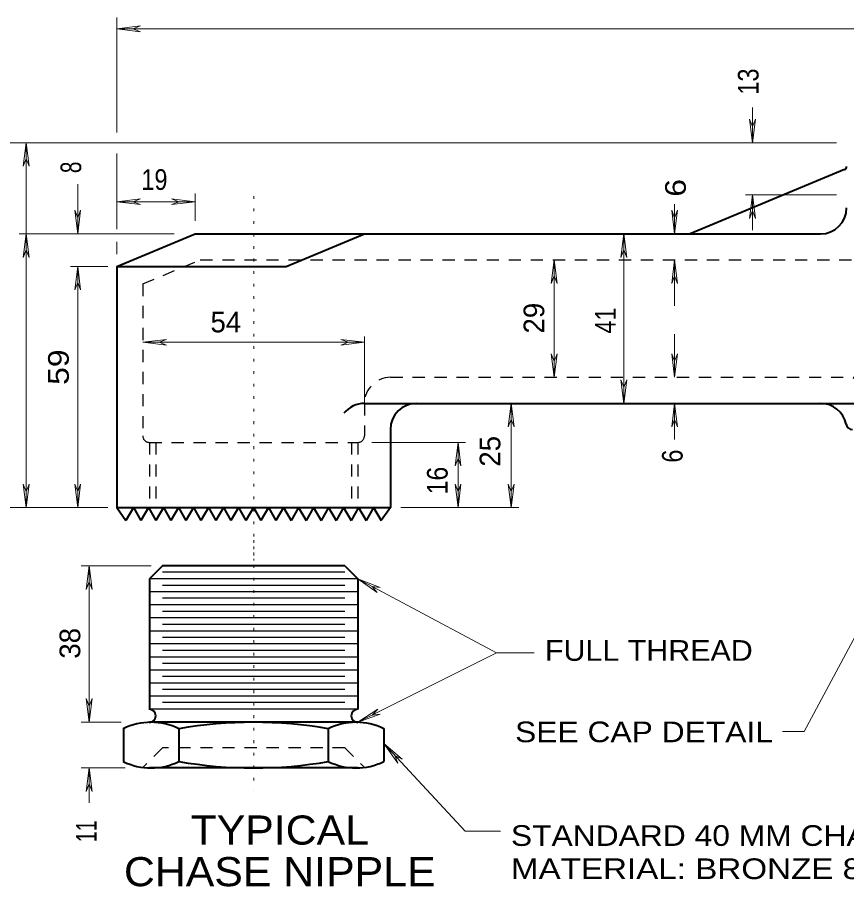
# Model space of a CAD drawing. Extents: x 312583 to 312854, y 144419 to 144597.
# Drawn here: x 312620.73 to 312651.22, y 144522.17 to 144554.13 of the extents above; entities that cross this region are included whole.
import ezdxf
from ezdxf.enums import TextEntityAlignment as Align

# ---------------------------------------------------------------- set-up
doc = ezdxf.new("R2010")
doc.units = 0
doc.header["$LTSCALE"] = 0.3
doc.linetypes.add('DOTTED', pattern=[1.5, 0.3, -1.2])
doc.linetypes.add('SHORT_DASHED', pattern=[2.7, 1.5, -1.2])
doc.layers.add('1', color=7, linetype='Continuous', lineweight=40)
doc.layers.add('2', color=7, linetype='Continuous', lineweight=13)

msp = doc.modelspace()

# ---------------------------------------------------------------- linework, layer by layer
at = {"layer": '1'}
for p, q in [((312651.1474, 144548.5342), (312645.4741, 144546.1729)), ((312624.3907, 144544.9769), (312627.2657, 144546.1729)), ((312627.2657, 144546.1729), (312650.2657, 144546.1729)), ((312630.6161, 144544.9769), (312633.4911, 144546.1729)), ((312624.3907, 144544.9769), (312630.6161, 144544.9769)), ((312633.4911, 144539.9399), (312651.6457, 144539.9399)), ((312634.4494, 144538.9815), (312634.4494, 144536.1065)), ((312624.3907, 144536.1065), (312624.7204, 144535.6312)), ((312624.9964, 144536.1065), (312624.7204, 144535.6312)), ((312624.9964, 144536.1065), (312625.2724, 144535.6312)), ((312625.5484, 144536.1065), (312625.2724, 144535.6312)), ((312625.5484, 144536.1065), (312625.8244, 144535.6312)), ((312626.1004, 144536.1065), (312625.8244, 144535.6312)), ((312626.1004, 144536.1065), (312626.3764, 144535.6312)), ((312626.6524, 144536.1065), (312626.3764, 144535.6312)), ((312626.6524, 144536.1065), (312626.9284, 144535.6312)), ((312627.2044, 144536.1065), (312626.9284, 144535.6312)), ((312627.2044, 144536.1065), (312627.4804, 144535.6312)), ((312627.7564, 144536.1065), (312627.4804, 144535.6312)), ((312627.7564, 144536.1065), (312628.0324, 144535.6312)), ((312628.3084, 144536.1065), (312628.0324, 144535.6312)), ((312628.3084, 144536.1065), (312628.5844, 144535.6312)), ((312628.8604, 144536.1065), (312628.5844, 144535.6312)), ((312628.8604, 144536.1065), (312629.1364, 144535.6312)), ((312629.4124, 144536.1065), (312629.1364, 144535.6312)), ((312629.4124, 144536.1065), (312629.6884, 144535.6312)), ((312629.9644, 144536.1065), (312629.6884, 144535.6312)), ((312629.9644, 144536.1065), (312630.2404, 144535.6312)), ((312630.5164, 144536.1065), (312630.2404, 144535.6312)), ((312630.5164, 144536.1065), (312630.7924, 144535.6312)), ((312631.0684, 144536.1065), (312630.7924, 144535.6312)), ((312631.0684, 144536.1065), (312631.3444, 144535.6312)), ((312631.6204, 144536.1065), (312631.3444, 144535.6312)), ((312631.6204, 144536.1065), (312631.8964, 144535.6312)), ((312632.1724, 144536.1065), (312631.8964, 144535.6312)), ((312632.1724, 144536.1065), (312632.4484, 144535.6312)), ((312632.7244, 144536.1065), (312632.4484, 144535.6312)), ((312632.7244, 144536.1065), (312633.0004, 144535.6312)), ((312633.2764, 144536.1065), (312633.0004, 144535.6312)), ((312633.2764, 144536.1065), (312633.5524, 144535.6312)), ((312633.8284, 144536.1065), (312633.5524, 144535.6312)), ((312633.8284, 144536.1065), (312634.1044, 144535.6312)), ((312634.4494, 144536.1065), (312634.1044, 144535.6312)), ((312626.0621, 144533.9675), (312625.5867, 144533.4845)), ((312632.7704, 144533.9675), (312626.0621, 144533.9675)), ((312632.7704, 144533.9675), (312633.2534, 144533.4845)), ((312625.5867, 144533.4845), (312625.5867, 144528.6929)), ((312633.2534, 144533.4845), (312633.2534, 144528.6929)), ((312633.2534, 144528.2175), (312625.5867, 144528.2175)), ((312624.6284, 144527.9799), (312624.6284, 144526.7762)), ((312626.6677, 144527.9799), (312626.6677, 144526.7762)), ((312632.1647, 144527.9799), (312632.1647, 144526.7762)), ((312634.2117, 144527.9799), (312634.2117, 144526.7762)), ((312633.2534, 144526.5385), (312625.5867, 144526.5385))]:
    msp.add_line(p, q, dxfattribs=at)
at = {"layer": '1', "linetype": 'DOTTED', "lineweight": 13}
for p, q in [((312629.4201, 144547.5605), (312629.4201, 144534.1592)), ((312629.4201, 144534.9105), (312629.4201, 144525.7029))]:
    msp.add_line(p, q, dxfattribs=at)
at = {"layer": '1', "linetype": 'SHORT_DASHED', "lineweight": 25}
for p, q in [((312625.3491, 144544.3329), (312627.4574, 144545.2145)), ((312627.4574, 144545.2145), (312651.9371, 144545.2145)), ((312625.3491, 144544.3329), (312625.3491, 144538.7439)), ((312634.4494, 144540.8982), (312653.7387, 144540.8982)), ((312633.4911, 144539.9399), (312633.4911, 144538.7439)), ((312625.5867, 144538.5062), (312633.2534, 144538.5062)), ((312625.5867, 144538.5062), (312625.5867, 144536.1065)), ((312625.8244, 144538.5062), (312625.8244, 144536.1065)), ((312633.0157, 144538.5062), (312633.0157, 144536.1065)), ((312633.2534, 144538.5062), (312633.2534, 144536.1065)), ((312626.0621, 144527.2745), (312625.3491, 144526.5539)), ((312632.7704, 144527.2745), (312626.0621, 144527.2745)), ((312632.7704, 144527.2745), (312633.4911, 144526.5539))]:
    msp.add_line(p, q, dxfattribs=at)
at = {"layer": '1', "lineweight": 25}
for p, q in [((312633.2534, 144533.4845), (312625.5867, 144533.4845)), ((312632.7704, 144533.7299), (312626.0621, 144533.7299)), ((312632.7704, 144533.2469), (312626.0621, 144533.2469)), ((312633.2534, 144533.0092), (312625.5867, 144533.0092)), ((312633.2534, 144532.5262), (312625.5867, 144532.5262)), ((312632.7704, 144532.7715), (312626.0621, 144532.7715)), ((312632.7704, 144532.2885), (312626.0621, 144532.2885)), ((312633.2534, 144532.0509), (312625.5867, 144532.0509)), ((312633.2534, 144531.5679), (312625.5867, 144531.5679)), ((312632.7704, 144531.8132), (312626.0621, 144531.8132)), ((312632.7704, 144531.3302), (312626.0621, 144531.3302)), ((312633.2534, 144531.0925), (312625.5867, 144531.0925)), ((312633.2534, 144530.6095), (312625.5867, 144530.6095)), ((312632.7704, 144530.8549), (312626.0621, 144530.8549)), ((312632.7704, 144530.3719), (312626.0621, 144530.3719)), ((312633.2534, 144530.1342), (312625.5867, 144530.1342)), ((312633.2534, 144529.6512), (312625.5867, 144529.6512)), ((312632.7704, 144529.8965), (312626.0621, 144529.8965)), ((312632.7704, 144529.4135), (312626.0621, 144529.4135)), ((312633.2534, 144529.1759), (312625.5867, 144529.1759)), ((312633.2534, 144528.6929), (312625.5867, 144528.6929)), ((312632.7704, 144528.9382), (312626.0621, 144528.9382))]:
    msp.add_line(p, q, dxfattribs=at)
at = {"layer": '1'}
msp.add_lwpolyline([(312624.3907, 144544.9769), (312624.3907, 144536.1065), (312634.4494, 144536.1065)], dxfattribs=at)
for centre, radius, start, end in [((312651.1004, 144548.6447), 0.1198, 292.61986, 0), ((312650.2619, 144547.1274), 0.9583, 270, 0), ((312633.4911, 144538.9815), 0.9583, 90, 141.73857), ((312635.4077, 144538.9815), 0.9583, 90, 180), ((312650.2619, 144538.9815), 0.9583, 11.53696, 90), ((312651.4356, 144539.2211), 0.2396, 191.53696, 270), ((312625.5829, 144528.4514), 0.2396, 270, 90), ((312633.2496, 144528.4514), 0.2396, 90, 270), ((312625.6461, 144525.8993), 2.3144, 63.80664, 116.19336), ((312629.4143, 144512.1802), 16.0335, 80.12254, 99.87746), ((312633.1863, 144525.8993), 2.3144, 63.80664, 116.19336), ((312625.6461, 144528.8491), 2.3144, 243.80664, 296.19336), ((312629.4143, 144542.5682), 16.0335, 260.12254, 279.87746), ((312633.1863, 144528.8491), 2.3144, 243.80664, 296.19336)]:
    msp.add_arc(centre, radius, start, end, dxfattribs=at)
at = {"layer": '1', "linetype": 'SHORT_DASHED', "lineweight": 25}
for centre, radius, start, end in [((312634.4494, 144539.9399), 0.9583, 90, 180), ((312651.2164, 144539.9399), 0.9583, 0, 90), ((312625.5848, 144538.7419), 0.2396, 180, 270), ((312633.2515, 144538.7419), 0.2396, 270, 0)]:
    msp.add_arc(centre, radius, start, end, dxfattribs=at)
at = {"layer": '2'}
for p, q in [((312624.3907, 144549.8989), (312624.3907, 144554.1309)), ((312624.3907, 144553.7092), (312625.2571, 144553.8165)), ((312624.3907, 144553.7092), (312688.1161, 144553.7092)), ((312624.3907, 144553.7092), (312625.2571, 144553.6019)), ((312625.2571, 144553.8165), (312624.9811, 144553.7092)), ((312625.2571, 144553.6019), (312624.9811, 144553.7092)), ((312647.7587, 144549.5232), (312647.7587, 144550.8189)), ((312647.6514, 144550.3895), (312647.7587, 144550.1135)), ((312647.7587, 144549.5232), (312647.6514, 144550.3895)), ((312647.8661, 144550.3895), (312647.7587, 144550.1135)), ((312647.7587, 144549.5232), (312647.8661, 144550.3895)), ((312650.8561, 144549.5232), (312618.7481, 144549.5232)), ((312621.0557, 144549.5232), (312620.9484, 144548.6569)), ((312621.0557, 144549.5232), (312621.1631, 144548.6569)), ((312624.3907, 144546.3415), (312624.3907, 144549.1245)), ((312620.9484, 144548.6569), (312621.0557, 144548.9329)), ((312621.1631, 144548.6569), (312621.0557, 144548.9329)), ((312622.9494, 144546.1729), (312622.9494, 144547.9991)), ((312627.2657, 144546.6559), (312627.2657, 144547.6525)), ((312647.5057, 144547.6065), (312650.8561, 144547.6065)), ((312647.7587, 144547.6065), (312647.6514, 144546.7402)), ((312647.7587, 144546.3032), (312647.7587, 144547.6065)), ((312647.7587, 144547.6065), (312647.8661, 144546.7402)), ((312624.3907, 144547.3535), (312625.2571, 144547.4609)), ((312624.3907, 144547.3535), (312627.2657, 144547.3535)), ((312624.3907, 144547.3535), (312625.2571, 144547.2462)), ((312625.2571, 144547.4609), (312624.9811, 144547.3535)), ((312625.2571, 144547.2462), (312624.9811, 144547.3535)), ((312626.3994, 144547.4609), (312626.6754, 144547.3535)), ((312627.2657, 144547.3535), (312626.3994, 144547.4609)), ((312626.3994, 144547.2462), (312626.6754, 144547.3535)), ((312627.2657, 144547.3535), (312626.3994, 144547.2462)), ((312644.8991, 144546.1729), (312644.8991, 144547.2615)), ((312622.8421, 144547.0392), (312622.9494, 144546.7632)), ((312622.9494, 144546.1729), (312622.8421, 144547.0392)), ((312623.0567, 144547.0392), (312622.9494, 144546.7632)), ((312622.9494, 144546.1729), (312623.0567, 144547.0392)), ((312644.7917, 144547.0392), (312644.8991, 144546.7632)), ((312644.8991, 144546.1729), (312644.7917, 144547.0392)), ((312645.0064, 144547.0392), (312644.8991, 144546.7632)), ((312644.8991, 144546.1729), (312645.0064, 144547.0392)), ((312647.6514, 144546.7402), (312647.7587, 144547.0162)), ((312647.8661, 144546.7402), (312647.7587, 144547.0162)), ((312626.4914, 144546.1729), (312620.7951, 144546.1729)), ((312621.0557, 144546.1729), (312620.9484, 144545.3065)), ((312621.0557, 144546.1729), (312621.1631, 144545.3065)), ((312643.0284, 144546.1729), (312642.9211, 144545.3065)), ((312643.0284, 144539.9399), (312643.0284, 144546.1729)), ((312643.0284, 144546.1729), (312643.1357, 144545.3065)), ((312620.9484, 144545.3065), (312621.0557, 144545.5825)), ((312621.1631, 144545.3065), (312621.0557, 144545.5825)), ((312624.3907, 144545.4215), (312624.3907, 144545.8739)), ((312642.9211, 144545.3065), (312643.0284, 144545.5825)), ((312643.1357, 144545.3065), (312643.0284, 144545.5825)), ((312624.0534, 144544.9769), (312622.6887, 144544.9769)), ((312622.9494, 144544.9769), (312622.8421, 144544.1105)), ((312622.9494, 144536.1065), (312622.9494, 144544.9769)), ((312622.9494, 144544.9769), (312623.0567, 144544.1105)), ((312640.4677, 144545.2145), (312640.3604, 144544.3482)), ((312640.4677, 144540.8982), (312640.4677, 144545.2145)), ((312640.4677, 144545.2145), (312640.5751, 144544.3482)), ((312644.8991, 144545.2145), (312644.7917, 144544.3482)), ((312644.8991, 144545.2145), (312645.0064, 144544.3482)), ((312644.8991, 144543.5279), (312644.8991, 144545.2145)), ((312640.3604, 144544.3482), (312640.4677, 144544.6242)), ((312640.5751, 144544.3482), (312640.4677, 144544.6242)), ((312644.7917, 144544.3482), (312644.8991, 144544.6242)), ((312645.0064, 144544.3482), (312644.8991, 144544.6242)), ((312622.8421, 144544.1105), (312622.9494, 144544.3865)), ((312623.0567, 144544.1105), (312622.9494, 144544.3865)), ((312633.4911, 144539.9399), (312633.4911, 144542.4009)), ((312644.8991, 144540.8982), (312644.8991, 144542.4852)), ((312625.3491, 144542.1862), (312626.2154, 144542.2935)), ((312633.4911, 144542.1862), (312625.3491, 144542.1862)), ((312625.3491, 144542.1862), (312626.2154, 144542.0789)), ((312626.2154, 144542.2935), (312625.9394, 144542.1862)), ((312626.2154, 144542.0789), (312625.9394, 144542.1862)), ((312632.6247, 144542.2935), (312632.9007, 144542.1862)), ((312633.4911, 144542.1862), (312632.6247, 144542.2935)), ((312632.6247, 144542.0789), (312632.9007, 144542.1862)), ((312633.4911, 144542.1862), (312632.6247, 144542.0789)), ((312640.3604, 144541.7645), (312640.4677, 144541.4885)), ((312640.4677, 144540.8982), (312640.3604, 144541.7645)), ((312640.5751, 144541.7645), (312640.4677, 144541.4885)), ((312640.4677, 144540.8982), (312640.5751, 144541.7645)), ((312644.7917, 144541.7645), (312644.8991, 144541.4885)), ((312644.8991, 144540.8982), (312644.7917, 144541.7645)), ((312645.0064, 144541.7645), (312644.8991, 144541.4885)), ((312644.8991, 144540.8982), (312645.0064, 144541.7645)), ((312642.9211, 144540.8062), (312643.0284, 144540.5302)), ((312643.0284, 144539.9399), (312642.9211, 144540.8062)), ((312643.1357, 144540.8062), (312643.0284, 144540.5302)), ((312643.0284, 144539.9399), (312643.1357, 144540.8062)), ((312638.8884, 144539.9399), (312638.7811, 144539.0735)), ((312638.8884, 144536.1065), (312638.8884, 144539.9399)), ((312638.8884, 144539.9399), (312638.9957, 144539.0735)), ((312644.8991, 144539.9399), (312644.7917, 144539.0735)), ((312644.8991, 144538.6135), (312644.8991, 144539.9399)), ((312644.8991, 144539.9399), (312645.0064, 144539.0735)), ((312638.7811, 144539.0735), (312638.8884, 144539.3495)), ((312638.9957, 144539.0735), (312638.8884, 144539.3495)), ((312644.7917, 144539.0735), (312644.8991, 144539.3495)), ((312645.0064, 144539.0735), (312644.8991, 144539.3495)), ((312633.7671, 144538.5062), (312637.2094, 144538.5062)), ((312636.9334, 144538.5062), (312636.8261, 144537.6399)), ((312636.9334, 144536.1065), (312636.9334, 144538.5062)), ((312636.9334, 144538.5062), (312637.0407, 144537.6399)), ((312636.8261, 144537.6399), (312636.9334, 144537.9159)), ((312637.0407, 144537.6399), (312636.9334, 144537.9159)), ((312620.9484, 144536.9729), (312621.0557, 144536.6969)), ((312621.0557, 144536.1065), (312620.9484, 144536.9729)), ((312621.1631, 144536.9729), (312621.0557, 144536.6969)), ((312621.0557, 144536.1065), (312621.1631, 144536.9729)), ((312622.8421, 144536.9729), (312622.9494, 144536.6969)), ((312622.9494, 144536.1065), (312622.8421, 144536.9729)), ((312623.0567, 144536.9729), (312622.9494, 144536.6969)), ((312622.9494, 144536.1065), (312623.0567, 144536.9729)), ((312636.8261, 144536.9729), (312636.9334, 144536.6969)), ((312636.9334, 144536.1065), (312636.8261, 144536.9729)), ((312637.0407, 144536.9729), (312636.9334, 144536.6969)), ((312636.9334, 144536.1065), (312637.0407, 144536.9729)), ((312638.7811, 144536.9729), (312638.8884, 144536.6969)), ((312638.8884, 144536.1065), (312638.7811, 144536.9729)), ((312638.9957, 144536.9729), (312638.8884, 144536.6969)), ((312638.8884, 144536.1065), (312638.9957, 144536.9729)), ((312624.0534, 144536.1065), (312618.7481, 144536.1065)), ((312634.8251, 144536.1065), (312639.1721, 144536.1065)), ((312625.6557, 144533.9675), (312623.0797, 144533.9675)), ((312623.3711, 144533.9675), (312623.2637, 144533.1012)), ((312623.3711, 144533.9675), (312623.3711, 144528.2175)), ((312623.3711, 144533.9675), (312623.4784, 144533.1012)), ((312633.2534, 144533.4845), (312633.9664, 144532.9862)), ((312633.2534, 144533.4845), (312634.0661, 144533.1702)), ((312623.2637, 144533.1012), (312623.3711, 144533.3772)), ((312623.4784, 144533.1012), (312623.3711, 144533.3772)), ((312633.9664, 144532.9862), (312633.7747, 144533.2085)), ((312634.0661, 144533.1702), (312633.7747, 144533.2085)), ((312638.3517, 144530.7629), (312639.7317, 144530.7629)), ((312623.2637, 144529.0839), (312623.3711, 144528.8079)), ((312623.3711, 144528.2175), (312623.2637, 144529.0839)), ((312623.4784, 144529.0839), (312623.3711, 144528.8079)), ((312623.3711, 144528.2175), (312623.4784, 144529.0839)), ((312633.2534, 144528.2175), (312633.9817, 144528.7005)), ((312633.9817, 144528.7005), (312633.7824, 144528.4782)), ((312633.2534, 144528.2175), (312634.0737, 144528.5089)), ((312634.0737, 144528.5089), (312633.7824, 144528.4782)), ((312624.5441, 144528.2175), (312623.0797, 144528.2175)), ((312634.2117, 144527.4279), (312634.7177, 144526.7149)), ((312634.2117, 144527.4279), (312634.8787, 144526.8605)), ((312634.7177, 144526.7149), (312634.6104, 144526.9909)), ((312634.8787, 144526.8605), (312634.6104, 144526.9909)), ((312624.6974, 144526.5385), (312623.0797, 144526.5385)), ((312623.3711, 144526.5385), (312623.2637, 144525.6722)), ((312623.3711, 144526.5385), (312623.3711, 144525.2505)), ((312623.3711, 144526.5385), (312623.4784, 144525.6722)), ((312623.2637, 144525.6722), (312623.3711, 144525.9482)), ((312623.4784, 144525.6722), (312623.3711, 144525.9482))]:
    msp.add_line(p, q, dxfattribs=at)
for points in [[(312621.0557, 144536.1065), (312621.0557, 144546.1729), (312621.0557, 144549.5232)], [(312633.2534, 144533.4845), (312638.3517, 144530.7629), (312633.2534, 144528.2175)], [(312648.8627, 144527.8802), (312649.6601, 144527.8802), (312652.6424, 144533.4232)], [(312634.2117, 144527.4279), (312637.2017, 144524.2079), (312638.4897, 144524.2079)]]:
    msp.add_lwpolyline(points, dxfattribs=at)

# ---------------------------------------------------------------- texts
for s, width, p in [('13', 0.85, (312647.9841, 144551.2903)), ('8', 0.75, (312623.0785, 144548.4049)), ('6 ', 1.15, (312645.3097, 144547.5375)), ('41', 0.85, (312642.7358, 144542.5029)), ('59 ', 1.15, (312622.6213, 144540.6211)), ('6', 0.85, (312645.1929, 144537.7604)), ('16', 0.9, (312636.5522, 144536.5922)), ('11', 0.7, (312623.6448, 144523.8105))]:
    msp.add_text(s, height=0.76, rotation=90, dxfattribs=dict(at, width=width)).set_placement(p)
for s, width, p in [('19', 0.85, (312625.2902, 144547.7881)), ('FULL THREAD', 1.1, (312640.1304, 144530.4749)), ('SEE CAP DETAIL', 1.15, (312639.0306, 144527.4811)), ('STANDARD 40 MM CHASE NIPPLE', 1.15, (312638.8787, 144523.6693)), ('MATERIAL: BRONZE 85-5-5-5.', 1.2, (312638.8787, 144522.4493))]:
    msp.add_text(s, height=0.76, dxfattribs=dict(at, width=width)).set_placement(p)
for s, p in [('29', (312640.1042, 144542.507)), ('25', (312638.4895, 144537.6115)), ('38', (312623.043, 144530.551))]:
    msp.add_text(s, height=0.76, rotation=90, dxfattribs=at).set_placement(p)
msp.add_text('54', height=0.76, dxfattribs=at).set_placement((312627.8314, 144542.5499))
at = {"layer": '2', "width": 1.1}
for s, p in [('TYPICAL', (312630.3784, 144523.7172)), ('CHASE NIPPLE', (312630.3784, 144522.1872))]:
    msp.add_text(s, height=1.07, dxfattribs=at).set_placement(p, align=Align.CENTER)

doc.saveas('drawing.dxf')
